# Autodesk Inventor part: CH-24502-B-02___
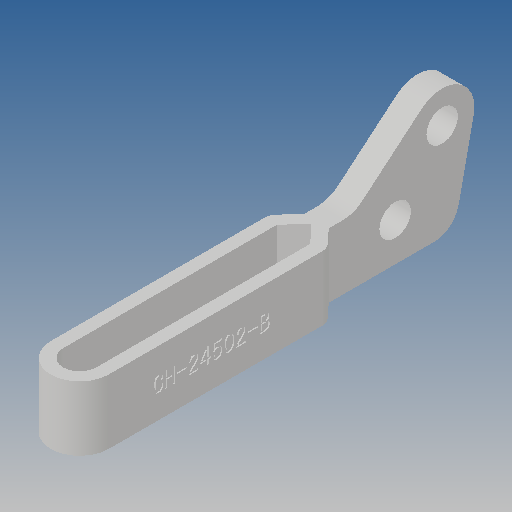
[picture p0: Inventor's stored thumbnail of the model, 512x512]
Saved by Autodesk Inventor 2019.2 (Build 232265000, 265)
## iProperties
Created: 2010-06
Part Number: CH-24502-B-02___
Material: Ogólny
Document SubType Name: Modeling
Designer: CADENGINEERING4
Density: 1 g/cm^3
Appearance: Domyślna
Author: CADENGINEERING4
Revision Number: ANY
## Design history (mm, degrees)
feature "NONE"
node "Bryła1"
